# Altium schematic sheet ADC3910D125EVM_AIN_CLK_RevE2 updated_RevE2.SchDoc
size A2; Date: Not shown in title block; ApprovedBy: Not shown in title block; CheckedBy: Not shown in title block; Author: Not shown in title block; CompanyName: Not shown in title block; Engineer: Not shown in title block; Organization: Not shown in title block; Address1: Not shown in title block; Address2: Not shown in title block; Address3: Not shown in title block; Address4: Not shown in title block; DocumentNumber: 1; Revision: Use project parameter SCH_Rev; SheetNumber: 4; SheetTotal: 7; PageSetup: Record=PageOptions¦CenterHorizontal=True¦CenterVertical=True¦PrintScale=0.69¦XCorrection=1.00¦YCorrection=1.00¦PrintKind=0¦BorderSize=5000000¦LeftOffset=0¦BottomOffset=0¦Orientation=2¦PaperLength=1000¦PaperWidth=1000¦Scale=100¦PaperSource=15¦PrintQuality=600¦MediaType=1¦DitherType=10¦PaperKind=Letter¦PrintScaleMode=1
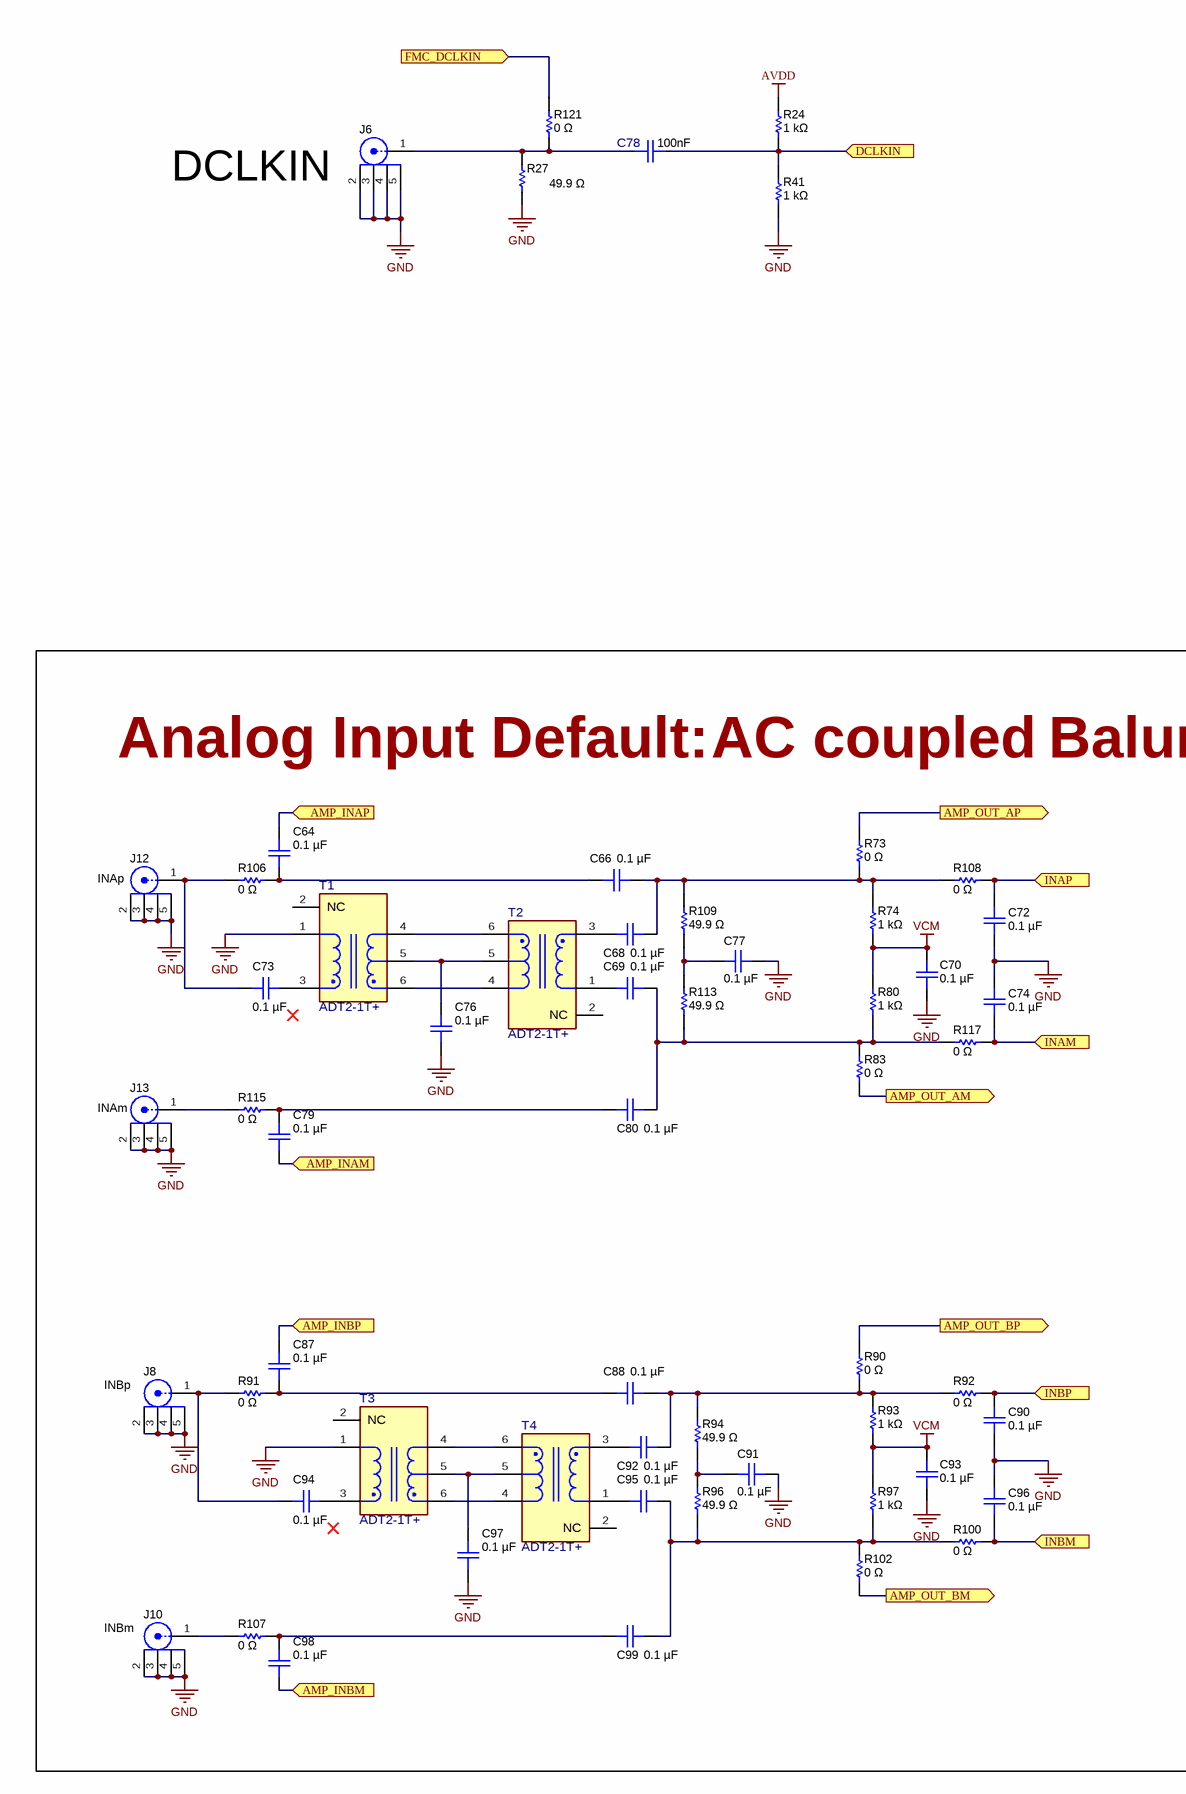
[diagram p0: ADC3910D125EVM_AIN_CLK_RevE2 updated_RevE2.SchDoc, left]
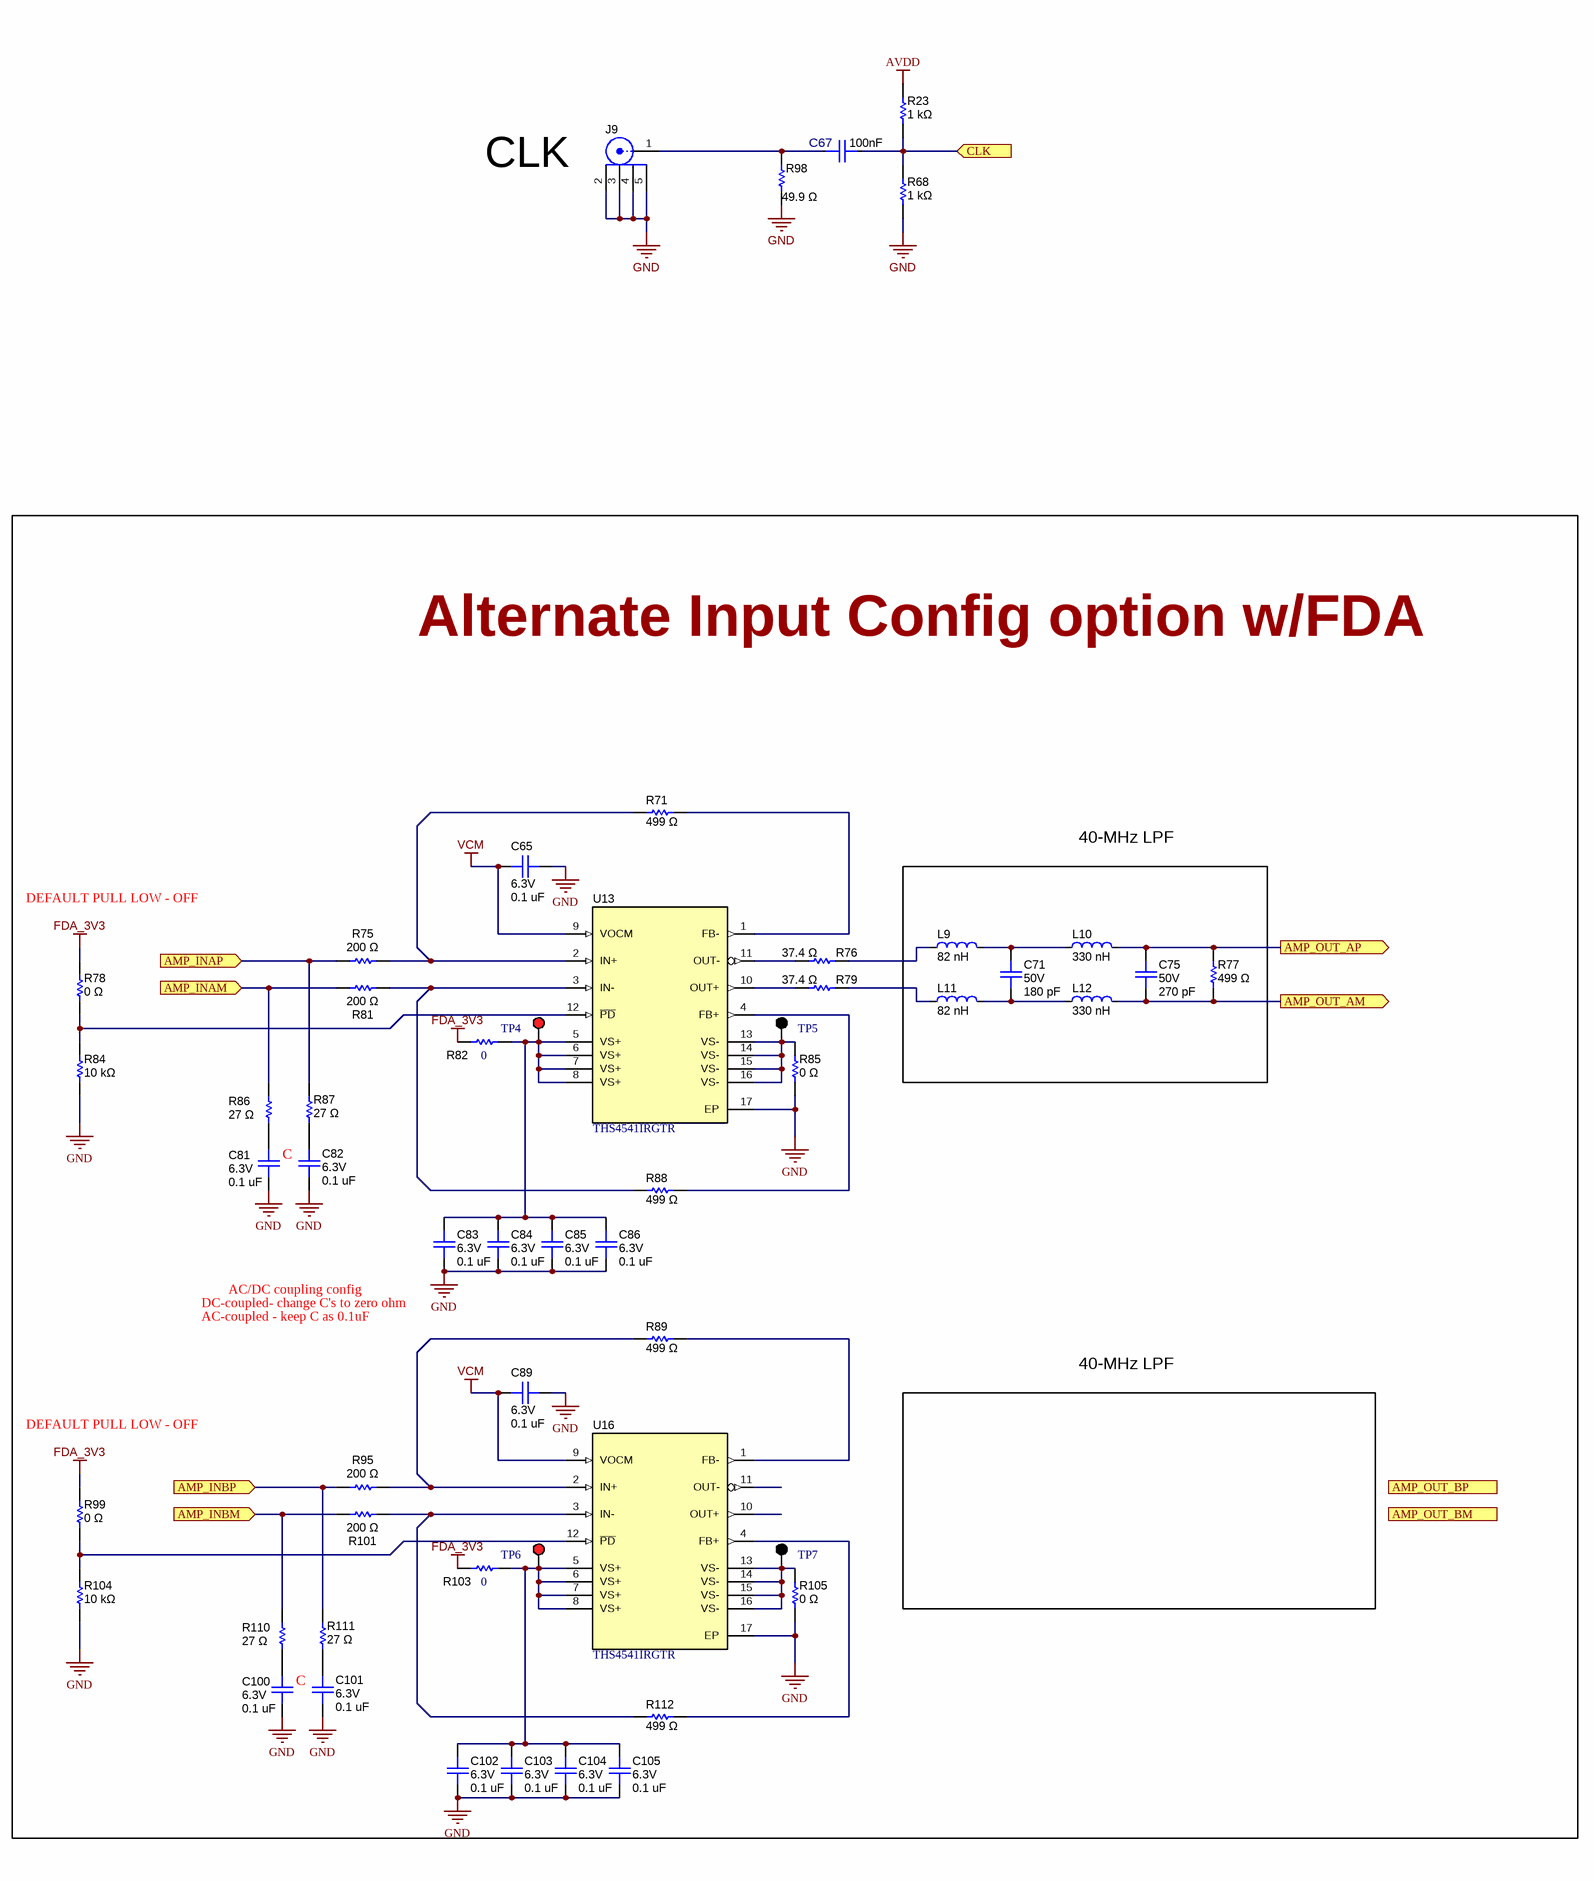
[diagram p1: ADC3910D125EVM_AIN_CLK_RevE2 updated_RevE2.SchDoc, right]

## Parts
C64  value 0.1 µF  [0402L]  (hidden comment: 0402YC104JAT4A)
C65  value 0.1 uF  Voltage - Rated: 6.3V  [0201]  (hidden comment: 02016D104KAT4A)
C66  value 0.1 µF  [0402L]  (hidden comment: 0402YC104JAT4A)
C67  Cap_F: 100nF  [FP-GCJ188R71C104KA01D_0603-MFG]  (hidden comment: GCJ188R71C104KA01D)
C68  value 0.1 µF  [0402L]  (hidden comment: 0402YC104JAT4A)
C69  value 0.1 µF  [0402L]  (hidden comment: 0402YC104JAT4A)
C70  value 0.1 µF  [0402L]  (hidden comment: 0402YC104JAT4A)
C71  value 180 pF  Voltage - Rated: 50V  [0402L_cap]  (hidden comment: 04025C181KAT2A)
C72  value 0.1 µF  [0402L]  (hidden comment: 0402YC104JAT4A)
C73  value 0.1 µF  [0402L]  (hidden comment: 0402YC104JAT4A)
C74  value 0.1 µF  [0402L]  (hidden comment: 0402YC104JAT4A)
C75  value 270 pF  Voltage - Rated: 50V  [0402L_cap]  (hidden comment: 04025C271JAT2A)
C76  value 0.1 µF  [0402L]  (hidden comment: 0402YC104JAT4A)
C77  value 0.1 µF  [0402L]  (hidden comment: 0402YC104JAT4A)
C78  Cap_F: 100nF  [FP-GCJ188R71C104KA01D_0603-MFG]  (hidden comment: GCJ188R71C104KA01D)
C79  value 0.1 µF  [0402L]  (hidden comment: 0402YC104JAT4A)
C80  value 0.1 µF  [0402L]  (hidden comment: 0402YC104JAT4A)
C81  value 0.1 uF  Voltage - Rated: 6.3V  [0201]  (hidden comment: 02016D104KAT4A)
C82  value 0.1 uF  Voltage - Rated: 6.3V  [0201]  (hidden comment: 02016D104KAT4A)
C83  value 0.1 uF  Voltage - Rated: 6.3V  [0201]  (hidden comment: 02016D104KAT4A)
C84  value 0.1 uF  Voltage - Rated: 6.3V  [0201]  (hidden comment: 02016D104KAT4A)
C85  value 0.1 uF  Voltage - Rated: 6.3V  [0201]  (hidden comment: 02016D104KAT4A)
C86  value 0.1 uF  Voltage - Rated: 6.3V  [0201]  (hidden comment: 02016D104KAT4A)
C87  value 0.1 µF  [0402L]  (hidden comment: 0402YC104JAT4A)
C88  value 0.1 µF  [0402L]  (hidden comment: 0402YC104JAT4A)
C89  value 0.1 uF  Voltage - Rated: 6.3V  [0201]  (hidden comment: 02016D104KAT4A)
C90  value 0.1 µF  [0402L]  (hidden comment: 0402YC104JAT4A)
C91  value 0.1 µF  [0402L]  (hidden comment: 0402YC104JAT4A)
C92  value 0.1 µF  [0402L]  (hidden comment: 0402YC104JAT4A)
C93  value 0.1 µF  [0402L]  (hidden comment: 0402YC104JAT4A)
C94  value 0.1 µF  [0402L]  (hidden comment: 0402YC104JAT4A)
C95  value 0.1 µF  [0402L]  (hidden comment: 0402YC104JAT4A)
C96  value 0.1 µF  [0402L]  (hidden comment: 0402YC104JAT4A)
C97  value 0.1 µF  [0402L]  (hidden comment: 0402YC104JAT4A)
C98  value 0.1 µF  [0402L]  (hidden comment: 0402YC104JAT4A)
C99  value 0.1 µF  [0402L]  (hidden comment: 0402YC104JAT4A)
C100  value 0.1 uF  Voltage - Rated: 6.3V  [0201]  (hidden comment: 02016D104KAT4A)
C101  value 0.1 uF  Voltage - Rated: 6.3V  [0201]  (hidden comment: 02016D104KAT4A)
C102  value 0.1 uF  Voltage - Rated: 6.3V  [0201]  (hidden comment: 02016D104KAT4A)
C103  value 0.1 uF  Voltage - Rated: 6.3V  [0201]  (hidden comment: 02016D104KAT4A)
C104  value 0.1 uF  Voltage - Rated: 6.3V  [0201]  (hidden comment: 02016D104KAT4A)
C105  value 0.1 uF  Voltage - Rated: 6.3V  [0201]  (hidden comment: 02016D104KAT4A)
J6  Text1: DCLKIN  [FP-132134-15_CONN_SMA_JACK-MFG]  (hidden comment: 132134-15)
J8  Text1: INBp  [FP-132134-15_CONN_SMA_JACK-MFG]  (hidden comment: 132134-15)
J9  Text1: CLK  [FP-132134-15_CONN_SMA_JACK-MFG]  (hidden comment: 132134-15)
J10  Text1: INBm  [FP-132134-15_CONN_SMA_JACK-MFG]  (hidden comment: 132134-15)
J12  Text1: INAp  [FP-132134-15_CONN_SMA_JACK-MFG]  (hidden comment: 132134-15)
J13  Text1: INAm  [FP-132134-15_CONN_SMA_JACK-MFG]  (hidden comment: 132134-15)
L9  value 82 nH  [TDK_IND_0402]  (hidden comment: MLG1005S82NJT000)
L10  value 330 nH  [TDK_IND_0402]  (hidden comment: MLG1005SR33JT000)
L11  value 82 nH  [TDK_IND_0402]  (hidden comment: MLG1005S82NJT000)
L12  value 330 nH  [TDK_IND_0402]  (hidden comment: MLG1005SR33JT000)
R23  value 1 kΩ  [0402L]  (hidden comment: ERA-2ARB102X)
R24  value 1 kΩ  [0402L]  (hidden comment: ERA-2ARB102X)
R27  value 49.9 Ω  [0603L]  (hidden comment: ERJ-3EKF49R9V)
R41  value 1 kΩ  [0402L]  (hidden comment: ERA-2ARB102X)
R68  value 1 kΩ  [0402L]  (hidden comment: ERA-2ARB102X)
R71  value 499 Ω  [0201]  (hidden comment: ERA-1AEB4990C)
R73  value 0 Ω  [0402L]  (hidden comment: ERJ-2GE0R00X)
R74  value 1 kΩ  [0402L]  (hidden comment: ERA-2ARB102X)
R75  value 200 Ω  [0201]  (hidden comment: ERA-1AEB201C)
R76  value 37.4 Ω  [0402L]  (hidden comment: ERJ-2RKF37R4X)
R77  value 499 Ω  [0402L]  (hidden comment: ERJ-2RKF4990X)
R78  value 0 Ω  [0201]  (hidden comment: ERJ-1GN0R00C)
R79  value 37.4 Ω  [0402L]  (hidden comment: ERJ-2RKF37R4X)
R80  value 1 kΩ  [0402L]  (hidden comment: ERA-2ARB102X)
R81  value 200 Ω  [0201]  (hidden comment: ERA-1AEB201C)
R82  ValueDisplayed: 0  [0201L]  (hidden comment: CRCW02010000Z0ED)
R83  value 0 Ω  [0402L]  (hidden comment: ERJ-2GE0R00X)
R84  value 10 kΩ  [0201]  (hidden comment: ERA-1AEB103C)
R85  value 0 Ω  [0201]  (hidden comment: ERJ-1GN0R00C)
R86  value 27 Ω  [0201]  (hidden comment: ERJ-U01F27R0C)
R87  value 27 Ω  [0201]  (hidden comment: ERJ-U01F27R0C)
R88  value 499 Ω  [0201]  (hidden comment: ERA-1AEB4990C)
R89  value 499 Ω  [0201]  (hidden comment: ERA-1AEB4990C)
R90  value 0 Ω  [0402L]  (hidden comment: ERJ-2GE0R00X)
R91  value 0 Ω  [0402L]  (hidden comment: ERJ-2GE0R00X)
R92  value 0 Ω  [0402L]  (hidden comment: ERJ-2GE0R00X)
R93  value 1 kΩ  [0402L]  (hidden comment: ERA-2ARB102X)
R94  value 49.9 Ω  [0402L]  (hidden comment: ERJ-2RKF49R9X)
R95  value 200 Ω  [0201]  (hidden comment: ERA-1AEB201C)
R96  value 49.9 Ω  [0402L]  (hidden comment: ERJ-2RKF49R9X)
R97  value 1 kΩ  [0402L]  (hidden comment: ERA-2ARB102X)
R98  value 49.9 Ω  [0603L]  (hidden comment: ERJ-3EKF49R9V)
R99  value 0 Ω  [0201]  (hidden comment: ERJ-1GN0R00C)
R100  value 0 Ω  [0402L]  (hidden comment: ERJ-2GE0R00X)
R101  value 200 Ω  [0201]  (hidden comment: ERA-1AEB201C)
R102  value 0 Ω  [0402L]  (hidden comment: ERJ-2GE0R00X)
R103  ValueDisplayed: 0  [0201L]  (hidden comment: CRCW02010000Z0ED)
R104  value 10 kΩ  [0201]  (hidden comment: ERA-1AEB103C)
R105  value 0 Ω  [0201]  (hidden comment: ERJ-1GN0R00C)
R106  value 0 Ω  [0402L]  (hidden comment: ERJ-2GE0R00X)
R107  value 0 Ω  [0402L]  (hidden comment: ERJ-2GE0R00X)
R108  value 0 Ω  [0402L]  (hidden comment: ERJ-2GE0R00X)
R109  value 49.9 Ω  [0402L]  (hidden comment: ERJ-2RKF49R9X)
R110  value 27 Ω  [0201]  (hidden comment: ERJ-U01F27R0C)
R111  value 27 Ω  [0201]  (hidden comment: ERJ-U01F27R0C)
R112  value 499 Ω  [0201]  (hidden comment: ERA-1AEB4990C)
R113  value 49.9 Ω  [0402L]  (hidden comment: ERJ-2RKF49R9X)
R115  value 0 Ω  [0402L]  (hidden comment: ERJ-2GE0R00X)
R117  value 0 Ω  [0402L]  (hidden comment: ERJ-2GE0R00X)
R121  value 0 Ω  [0603L]  (hidden comment: ERJ-U030R00V)
T1  ADT2-1T+  [FP-ADT2-1T+_SMD6-MFG]
T2  ADT2-1T+  [FP-ADT2-1T+_SMD6-MFG]
T3  ADT2-1T+  [FP-ADT2-1T+_SMD6-MFG]
T4  ADT2-1T+  [FP-ADT2-1T+_SMD6-MFG]
TP4  5010  [Keystone5010]  (value not drawn)
TP5  5011  [Keystone5011]  (value not drawn)
TP6  5010  [Keystone5010]  (value not drawn)
TP7  5011  [Keystone5011]  (value not drawn)
U13  THS4541IRGTR  [RGT0016A_NV]
U16  THS4541IRGTR  [RGT0016A_NV]

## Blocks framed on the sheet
Alternate Input Config option w/FDA: C65 C71 C75 C81-C86 C89 C100-C105 L9-L12 R71 R75-R79 R81 R82 R84-R89 R95 R99 R101 R103-R105 R110-R112 TP4-TP7 U13 U16

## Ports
AMP_INAM (in, see 4), AMP_INAP (in, see 4), AMP_INBM (in, see 4), AMP_INBP (in, see 4), AMP_OUT_AM (out, see 4), AMP_OUT_AP (out, see 4), AMP_OUT_BM (out, see 4), AMP_OUT_BP (out, see 4), CLK (in, see 5), DCLKIN (in, see 5), FMC_DCLKIN (in, see 6), INAM (in, see 5), INAP (in, see 5), INBM (in, see 5), INBP (in, see 5)

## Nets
AVDD: R23.2 R24.2
FDA_3V3: R78.2 R82.1 R99.2 R103.1
GND: C65.1 C70.2 C72.1 C74.2 C76.1 C77.1 C81.1 C82.2 C83.1 C84.1 C85.1 C86.1 C89.1 C90.1 C91.1 C93.2 C96.2 C97.1 C100.1 C101.2 C102.1 C103.1 C104.1 C105.1 J6.2 J6.3 J6.4 J6.5 J8.2 J8.3 J8.4 J8.5 J9.2 J9.3 J9.4 J9.5 J10.2 J10.3 J10.4 J10.5 J12.2 J12.3 J12.4 J12.5 J13.2 J13.3 J13.4 J13.5 R27.1 R41.1 R68.1 R84.1 R85.1 R98.1 R104.1 R105.1 T1.1(PRIMARY) T3.1(PRIMARY) U13.17(EP) U16.17(EP)
VCM: C65.2 C70.1 C89.2 C93.1 R74.1 R80.2 R93.1 R97.2 U13.9(VOCM) U16.9(VOCM)
AMP_INAM: C79.1 R81.1 R86.2 ; port AMP_INAM
AMP_INAP: C64.2 R75.1 R87.1 ; port AMP_INAP
AMP_INBM: C98.1 R101.1 R110.2 ; port AMP_INBM
AMP_INBP: C87.2 R95.1 R111.1 ; port AMP_INBP
AMP_OUT_AM: C75.1 L12.2 R77.1 R83.1 ; port AMP_OUT_AM
AMP_OUT_AP: C75.2 L10.2 R73.2 R77.2 ; port AMP_OUT_AP
AMP_OUT_BM: R102.1 ; port AMP_OUT_BM
AMP_OUT_BP: R90.2 ; port AMP_OUT_BP
CLK: C67.2 R23.1 R68.2 ; port CLK
DCLKIN: C78.2 R24.1 R41.2 ; port DCLKIN
FMC_DCLKIN: R121.2 ; port FMC_DCLKIN
INAM: C74.1 R117.2 ; port INAM
INAP: C72.2 R108.2 ; port INAP
INBM: C96.1 R100.2 ; port INBM
INBP: C90.2 R92.2 ; port INBP
NetC64_1: C64.1 C66.1 R106.2
NetC66_2: C66.2 C68.2 R73.1 R74.2 R108.1 R109.2
NetC67_1: C67.1 J9.1 R98.2
NetC68_1: C68.1 T2.3(PRIMARY_DOT)
NetC69_1: C69.1 T2.1(PRIMARY)
NetC69_2: C69.2 C80.2 R80.1 R83.2 R113.1 R117.1
NetC71_1: C71.1 L11.2 L12.1
NetC71_2: C71.2 L9.2 L10.1
NetC73_1: C73.1 J12.1 R106.1
NetC73_2: C73.2 T1.3(PRIMARY_DOT)
NetC76_2: C76.2 T1.5(SECONDARY_CT) T2.5(SECONDARY_CT)
NetC77_2: C77.2 R109.1 R113.2
NetC78_1: C78.1 J6.1 R27.2 R121.1
NetC79_2: C79.2 C80.1 R115.2
NetC81_2: C81.2 R86.1
NetC82_1: C82.1 R87.2
NetC83_2: C83.2 C84.2 C85.2 C86.2 R82.2 TP4.1 U13.5(VS+) U13.6(VS+) U13.7(VS+) U13.8(VS+)
NetC87_1: C87.1 C88.1 R91.2
NetC88_2: C88.2 C92.2 R90.1 R92.1 R93.2 R94.2
NetC91_2: C91.2 R94.1 R96.2
NetC92_1: C92.1 T4.3(PRIMARY_DOT)
NetC94_1: C94.1 J8.1 R91.1
NetC94_2: C94.2 T3.3(PRIMARY_DOT)
NetC95_1: C95.1 T4.1(PRIMARY)
NetC95_2: C95.2 C99.2 R96.1 R97.1 R100.1 R102.2
NetC97_2: C97.2 T3.5(SECONDARY_CT) T4.5(SECONDARY_CT)
NetC98_2: C98.2 C99.1 R107.2
NetC100_2: C100.2 R110.1
NetC101_1: C101.1 R111.2
NetC102_2: C102.2 C103.2 C104.2 C105.2 R103.2 TP6.1 U16.5(VS+) U16.6(VS+) U16.7(VS+) U16.8(VS+)
NetJ10_1: J10.1 R107.1
NetJ13_1: J13.1 R115.1
NetL9_1: L9.1 R76.2
NetL11_1: L11.1 R79.2
NetR71_1: R71.1 R75.2 U13.2(IN+)
NetR71_2: R71.2 U13.1(FB-)
NetR76_1: R76.1 U13.11(OUT-)
NetR78_1: R78.1 R84.2 U13.12(~{PD})
NetR79_1: R79.1 U13.10(OUT+)
NetR81_2: R81.2 R88.1 U13.3(IN-)
NetR85_2: R85.2 TP5.1 U13.13(VS-) U13.14(VS-) U13.15(VS-) U13.16(VS-)
NetR88_2: R88.2 U13.4(FB+)
NetR89_1: R89.1 R95.2 U16.2(IN+)
NetR89_2: R89.2 U16.1(FB-)
NetR99_1: R99.1 R104.2 U16.12(~{PD})
NetR101_2: R101.2 R112.1 U16.3(IN-)
NetR105_2: R105.2 TP7.1 U16.13(VS-) U16.14(VS-) U16.15(VS-) U16.16(VS-)
NetR112_2: R112.2 U16.4(FB+)
NetT1_4: T1.4(SECONDARY) T2.6(SECONDARY_DOT)
NetT1_6: T1.6(SECONDARY_DOT) T2.4(SECONDARY)
NetT3_4: T3.4(SECONDARY) T4.6(SECONDARY_DOT)
NetT3_6: T3.6(SECONDARY_DOT) T4.4(SECONDARY)

Not connected (* = marked no-connect by the designer): T1 2(NC); T2 2(NC); T3 2(NC); T4 2(NC); U16 10(OUT+) 11(OUT-)

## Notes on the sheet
- Analog Input Default:
- AC coupled
- Balun
- 40-MHz LPF
- DEFAULT PULL LOW - OFF
- C
- (near C83) DC-coupled- change C's to zero ohm
- AC-coupled - keep C as 0.1uF
- AC/DC coupling config

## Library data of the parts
C64 C66 C68-C70 C72-C74 C76 C77 C79 C80 C87 C88 C90-C99 = capcc01284: CAP CER 0.1UF 16V X7R 0402; Manufacturer: KYOCERA AVX; SizeZ_mm: 0.56; Tolerance: ±5%; SizeX_mm: 1; SizeY_mm: 0.5
C65 C81-C86 C89 C100-C105 = capcc01375: CAP CER 0.1UF 6.3V X5R 0201; Manufacturer: KYOCERA AVX; Tolerance: ±10%; SizeX_mm: 0.6; SizeY_mm: 0.3; SizeZ_mm: 0.33; CompType: Capacitor Ceramic
C67 C78 = CMP-0090409-1: 0.1µF ±10% 16V Ceramic Capacitor X7R 0603 (1608 Metric); Manufacturer: Murata Electronics North America; AEC Grade: Grade 1; ValueDisplayed: 0.1uF; AEC Qualified: Yes; SizeZ_mm: 0.9mm; TempCo: 15%; Value: 100nF
C71 = capcc06444: CAP CER 180PF 50V X7R 0402; Manufacturer: KYOCERA AVX; CompType: Capacitor Ceramic; Tolerance: ±10%; SizeX_mm: 1; SizeY_mm: 0.5; SizeZ_mm: 0.56
C75 = capcc00002: CAP CER 270PF 50V X7R 0402; Manufacturer: KYOCERA AVX; CompType: Capacitor Ceramic; Tolerance: ±5%; SizeX_mm: 1; SizeY_mm: 0.5; SizeZ_mm: 0.56
J6 J8-J10 J12 J13 = connector00001: SMA Connector Jack, Female Socket 50Ohm Surface Mount, Through Hole Solder; Manufacturer: Amphenol RF; CompType: RF Connector
L9 L11 = indrf00701: FIXED IND 82NH 200MA 1.6 OHM SMD; Manufacturer: TDK Corporation; CompType: Inductor RF; Material: Ceramic, Non-Magnetic; Tolerance: ±5%; DC Resistance (DCR): 1.6 Ω; Q @ Freq: 8 @ 100MHz; Frequency - Self Resonant: 700 MHz; SizeX_mm: 1; SizeY_mm: 0.5; SizeZ_mm: 0.55
L10 L12 = indrf00703: FIXED IND 330NH 50MA 7 OHM SMD; Manufacturer: TDK Corporation; CompType: Inductor RF; Material: Ceramic, Non-Magnetic; Tolerance: ±5%; DC Resistance (DCR): 7 Ω; Frequency - Self Resonant: 350 MHz; SizeX_mm: 1; SizeY_mm: 0.5; SizeZ_mm: 0.55
R23 R68 R74 R80 R93 R97 = RSMD040201174: RES SMD 1K OHM 0.1% 1/16W 0402; Manufacturer: Panasonic Electronic Components; Power (Watts): 0.063W, 1/16W; Temperature Coefficient: ±10ppm/°C; SizeX_mm: 1; SizeY_mm: 0.5; SizeZ_mm: 0.4
R24 R41 = RSMD040200016: RES SMD 1K OHM 0.1% 1/16W 0402; Manufacturer: Panasonic Electronic Components; CompType: Resistor SMD; Power (Watts): 0.063W, 1/16W; Temperature Coefficient: ±10ppm/°C; SizeX_mm: 1; SizeY_mm: 0.5; SizeZ_mm: 0.4
R27 R98 = RSMD060309158: RES SMD 49.9 OHM 1% 1/10W 0603; Manufacturer: Panasonic Electronic Components; Power (Watts): 0.1W, 1/10W; Temperature Coefficient: ±100ppm/°C; SizeX_mm: 1.6; SizeY_mm: 0.8; SizeZ_mm: 0.55
R71 R88 R89 R112 = RSMD020101661: RES SMD 499 OHM 0.1% 1/20W 0201; Manufacturer: Panasonic Electronic Components; CompType: Resistor SMD; Power (Watts): 0.05W, 1/20W; Temperature Coefficient: ±25ppm/°C
R73 R83 R90-R92 R100 R102 R106-R108 R115 R117 = RSMD040200001: RES SMD 0 OHM JUMPER 1/10W 0402; Manufacturer: Panasonic Electronic Components; Power (Watts): 0.1W, 1/10W; SizeX_mm: 1; SizeY_mm: 0.5; SizeZ_mm: 0.4
R75 R81 R95 R101 = RSMD020101507: RES SMD 200 OHM 0.1% 1/20W 0201; Manufacturer: Panasonic Electronic Components; CompType: Resistor SMD; Power (Watts): 0.05W, 1/20W; Temperature Coefficient: ±25ppm/°C
R76 R79 = RSMD040202422: RES SMD 37.4 OHM 1% 1/10W 0402; Manufacturer: Panasonic Electronic Components; CompType: Resistor SMD; Power (Watts): 0.1W, 1/10W; Temperature Coefficient: ±100ppm/°C; SizeX_mm: 1; SizeY_mm: 0.5; SizeZ_mm: 0.4
R77 = RSMD040202923: RES SMD 499 OHM 1% 1/10W 0402; Manufacturer: Panasonic Electronic Components; CompType: Resistor SMD; Power (Watts): 0.1W, 1/10W; Temperature Coefficient: ±100ppm/°C; SizeX_mm: 1; SizeY_mm: 0.5; SizeZ_mm: 0.4
R78 R99 = RSMD020101699: RES SMD 0 OHM JUMPER 1/20W 0201; Manufacturer: Panasonic Electronic Components; CompType: Resistor SMD; Power (Watts): 0.05W, 1/20W
R82 R103 = CMP-0027008-4: RES, 0, 5%, 0.05 W, 0201; Manufacturer: Vishay-Dale; Power_W: 50mW; TempCo: ppm/C; Value_Code: 0000; Value: 0; EIA_Code: E24; SizeX_mm: 0.6; SizeY_mm: 0.3; SizeZ_mm: 0.26; Value2: 0.05W; SizeArea_mm2: 0.18; AEC Qualified: N; AEC Category: Q200
R84 R104 = RSMD020101470: RES SMD 10K OHM 0.1% 1/20W 0201; Manufacturer: Panasonic Electronic Components; CompType: Resistor SMD; Power (Watts): 0.05W, 1/20W; Temperature Coefficient: ±25ppm/°C
R85 R105 = RSMD020101699: RES SMD 0 OHM JUMPER 1/20W 0201; Manufacturer: Panasonic Electronic Components; Power (Watts): 0.05W, 1/20W; CompType: Resistor SMD
R86 R87 R110 R111 = RSMD020100256: RES 27 OHM 1% 1/20W 0201 SMD; Manufacturer: Panasonic Electronic Components; CompType: Resistor SMD; Power (Watts): 0.05W, 1/20W; Temperature Coefficient: ±200ppm/°C
R94 R96 R109 R113 = RSMD040200376: RES SMD 49.9 OHM 1% 1/10W 0402; Manufacturer: Panasonic Electronic Components; Power (Watts): 0.1W, 1/10W; Temperature Coefficient: ±100ppm/°C; SizeX_mm: 1; SizeY_mm: 0.5; SizeZ_mm: 0.4
R121 = RSMD060312253: RES 0 OHM JUMPER 0603 SMD; Manufacturer: Panasonic Electronic Components; Power (Watts): 0.1W, 1/10W; Temperature Coefficient: ±200ppm/°C; SizeX_mm: 1.6; SizeY_mm: 0.8; SizeZ_mm: 0.55
T1-T4 = CMP-0089317-2: RF Transformer Surface Mount 50Ω 4.5 to 3000 MHz; Manufacturer: Mini-Circuits; Return Loss: 7.38dB; SizeZ_mm: 2.84mm; Insertion Loss: 0.3-1.25dB; AEC Qualified: No; Frequency_Fixed: 0.4-450MHz; Ns1toNp: 2:1:1; DCR_ohm: 2
TP4 TP6 = CMP-0055147-2: Test Point, Multipurpose, Red, TH; Manufacturer: Keystone Electronics; CT: TRUE; ContactFinish: Silver; Green_Lifecycle: Active; CNHeader: FALSE; Green_REACh: Passed
TP5 TP7 = CMP-0055148-2: Test Point, Multipurpose, Black, TH; Manufacturer: Keystone Electronics; CNHeader: FALSE; Green_Lifecycle: Active; Green_REACh: Passed; ContactFinish: Silver; CT: TRUE
U13 U16 = CMP-0065559-3: High-Speed Differential I/O Amplifier, RGT0016A (VQFN-16); Alternate PartNumber: THS4541IRGTT; Manufacturer: Texas Instruments; SizeZ_mm: 4; SizeArea_mm2: 16; CompType: IC; SizeAreaWB_mm2: 25; AEC Category: Q200; AEC Qualified: N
